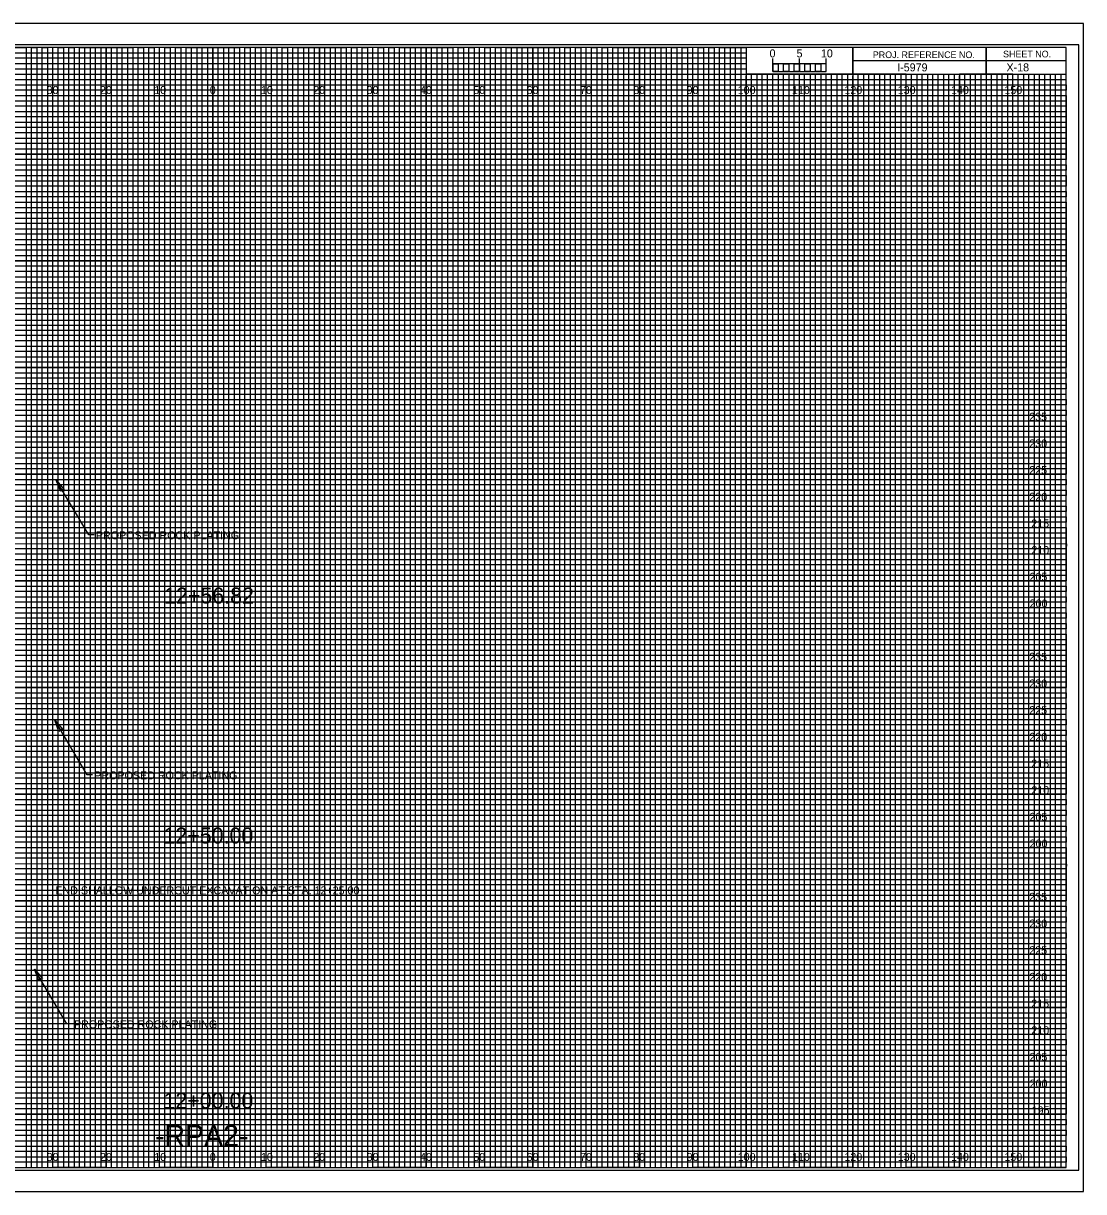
# Model space of a CAD drawing. Extents: x -13 to 323, y -5 to 434.
# Drawn here: x 124.5 to 323.3, y 215.5 to 434.5 of the extents above; entities that cross this region are included whole.
import ezdxf

# ---------------------------------------------------------------- set-up
doc = ezdxf.new("R2010")
doc.units = 0
for name, color, linetype in [('Prop CMT Concrete Structures', 7, 'Continuous'), ('Prop Terminator CELL', 7, 'Continuous'), ('Prop XS Alignment Label', 7, 'Continuous'), ('Prop XS Bar Scale Labels', 7, 'Continuous'), ('Prop XS Elevation Labels', 7, 'Continuous'), ('Prop XS Hydro Elevations', 7, 'Continuous'), ('Prop XS Offset Labels', 7, 'Continuous'), ('Prop XS Project Number', 7, 'Continuous'), ('Prop XS SE Text', 7, 'Continuous'), ('Prop XS Sheet Number', 7, 'Continuous'), ('Prop XS Station Labels', 7, 'Continuous'), ('Sheet Cross Section CELL', 7, 'Continuous'), ('Sheet Cross Section Grid Major CELL', 7, 'Continuous'), ('Sheet Cross Section Grid Middle CELL', 7, 'Continuous'), ('Sheet Cross Section Grid Minor 1 CELL', 7, 'Continuous'), ('Sheet Cross Section Grid Minor 2 CELL', 7, 'Continuous'), ('Sheet Cross Section Scale CELL', 7, 'Continuous'), ('Sheet Cutting Line CELL', 7, 'Continuous'), ('Sheet DOT Grid CELL', 7, 'Continuous'), ('Sheet Plot Border Inside CELL', 7, 'Continuous'), ('Sheet Plot Border Outside CELL', 7, 'Continuous')]:
    doc.layers.add(name, color=color, linetype=linetype)

msp = doc.modelspace()

# ---------------------------------------------------------------- linework, layer by layer
at = {"layer": 'Prop CMT Concrete Structures'}
for points in [[(137.78, 338.61), (136.76, 338.61), (130.68, 348.85)], [(137.47, 293.61), (136.45, 293.61), (130.37, 303.86)], [(133.67, 246.94), (132.65, 246.94), (126.57, 257.18)]]:
    msp.add_lwpolyline(points, dxfattribs=at)
at = {"layer": 'Prop Terminator CELL'}
for points in [[(131.5, 346.72), (130.68, 348.85), (132.18, 347.11), (131.69, 347.15)], [(131.18, 301.73), (130.37, 303.86), (131.87, 302.12), (131.38, 302.16)], [(127.39, 255.05), (126.57, 257.18), (128.07, 255.44), (127.58, 255.49)]]:
    msp.add_lwpolyline(points, close=True, dxfattribs=at)
at = {"layer": 'Sheet Cross Section CELL'}
for p, q in [((305, 430), (305, 425)), ((305, 425), (305, 430)), ((280, 427.5), (280, 425)), ((320, 427.49), (280, 427.49)), ((280, 425), (320, 425))]:
    msp.add_line(p, q, dxfattribs=at)
for points in [[(320, 430), (0, 430), (0, 220), (320, 220)], [(280, 430), (260, 430), (260, 425.03), (280, 425.03)], [(320, 430), (280, 430), (280, 425), (320, 425)]]:
    msp.add_lwpolyline(points, close=True, dxfattribs=at)
at = {"layer": 'Sheet Cross Section Grid Major CELL'}
for p, q in [((130, 430), (120, 430)), ((130, 220), (130, 430)), ((150, 430), (140, 430)), ((140, 430), (140, 220)), ((150, 220), (150, 430)), ((170, 430), (160, 430)), ((160, 430), (160, 220)), ((170, 220), (170, 430)), ((190, 430), (180, 430)), ((180, 430), (180, 220)), ((190, 220), (190, 430)), ((210, 430), (200, 430)), ((200, 430), (200, 220)), ((210, 220), (210, 430)), ((230, 430), (220, 430)), ((220, 430), (220, 220)), ((230, 220), (230, 430)), ((250, 430), (240, 430)), ((240, 430), (240, 220)), ((250, 220), (250, 430)), ((260, 430), (260, 220)), ((270, 220), (270, 425)), ((290, 425), (280, 425)), ((280, 425), (280, 220)), ((290, 220), (290, 425)), ((310, 425), (300, 425)), ((300, 425), (300, 220)), ((310, 220), (310, 425)), ((140, 220), (130, 220)), ((160, 220), (150, 220)), ((180, 220), (170, 220)), ((200, 220), (190, 220)), ((220, 220), (210, 220)), ((240, 220), (230, 220)), ((260, 220), (250, 220)), ((280, 220), (270, 220)), ((300, 220), (290, 220)), ((320, 220), (310, 220)), ((320, 220), (320, 220))]:
    msp.add_line(p, q, dxfattribs=at)
for points in [[(0, 420), (320, 420), (320, 410), (0, 410)], [(0, 400), (320, 400), (320, 390), (0, 390)], [(0, 380), (320, 380), (320, 370), (0, 370)], [(0, 360), (320, 360), (320, 350), (0, 350)], [(0, 340), (320, 340), (320, 330), (0, 330)], [(0, 320), (320, 320), (320, 310), (0, 310)], [(0, 300), (320, 300), (320, 290), (0, 290)], [(0, 280), (320, 280), (320, 270), (0, 270)], [(0, 260), (320, 260), (320, 250), (0, 250)], [(0, 240), (320, 240), (320, 230), (0, 230)]]:
    msp.add_lwpolyline(points, dxfattribs=at)
at = {"layer": 'Sheet Cross Section Grid Middle CELL'}
for points in [[(115, 430), (125, 430), (125, 220), (135, 220), (135, 430), (145, 430), (145, 220), (155, 220), (155, 430), (165, 430), (165, 220), (175, 220), (175, 430), (185, 430), (185, 220), (195, 220), (195, 430), (205, 430), (205, 220), (215, 220), (215, 430), (225, 430), (225, 220), (235, 220), (235, 430), (245, 430), (245, 220), (255, 220), (255, 430), (259.93, 430), (260, 430), (260, 425), (264.99, 425), (264.99, 220), (275, 220), (275, 425), (285, 425), (285, 220), (295, 220), (295, 425), (305, 425), (305, 220), (315, 220), (315, 425)], [(0, 425), (275, 425)], [(0, 405), (320, 405), (320, 415), (0, 415)], [(0, 385), (320, 385), (320, 395), (0, 395)], [(0, 365), (320, 365), (320, 375), (0, 375)], [(0, 345), (320, 345), (320, 355), (0, 355)], [(0, 325), (320, 325), (320, 335), (0, 335)], [(0, 305), (320, 305), (320, 315), (0, 315)], [(0, 285), (320, 285), (320, 295), (0, 295)], [(0, 265), (320, 265), (320, 275), (0, 275)], [(0, 245), (320, 245), (320, 255), (0, 255)], [(0, 225), (320, 225), (320, 235), (0, 235)]]:
    msp.add_lwpolyline(points, dxfattribs=at)
at = {"layer": 'Sheet Cross Section Grid Minor 1 CELL'}
for p, q in [((0, 429), (260, 429)), ((260, 427.98), (0, 427.98)), ((260, 429), (260, 427.98)), ((0, 427), (260, 427)), ((260, 425.89), (0, 425.89)), ((260, 427), (260, 425.89)), ((0, 424), (320, 424))]:
    msp.add_line(p, q, dxfattribs=at)
for points in [[(0, 423), (270, 423), (320, 423), (320, 422), (0, 422)], [(0, 421), (320, 421), (320, 419), (0, 419)], [(0, 418), (320, 418), (320, 417), (0, 416.98)], [(0, 416), (320, 416), (320, 414), (0, 414)], [(0, 413), (320, 413), (320, 412), (0, 412)], [(0, 411), (320, 411), (320, 409), (0, 409)], [(0, 408), (320, 408), (320, 407), (0, 407)], [(0, 406), (320, 406), (320, 404), (0, 404)], [(0, 403), (320, 403), (320, 402), (0, 402)], [(0, 401), (320, 401), (320, 399), (0, 399)], [(0, 398), (320, 398), (320, 397), (0, 397)], [(0, 396), (320, 396), (320, 393.95), (320, 393), (320, 392), (0, 392)], [(0, 394), (320, 394), (320, 393), (0, 393)], [(0, 391), (320, 391), (320, 389), (0, 389.03)], [(0, 389.03), (320, 389), (320, 388), (0, 388)], [(0, 387), (320, 387), (320, 386), (0, 386)], [(0, 384), (320, 384), (320, 383), (0, 383)], [(0, 382), (320, 382), (320, 381), (0, 381)], [(-0.07, 378.89), (320, 378.89), (320, 377.88), (-0.07, 377.88)], [(0, 377), (320, 377), (320, 376), (0, 376)], [(0, 374), (320, 374), (320, 373), (0, 373)], [(0, 372), (320, 372), (320, 371), (0, 371)], [(0, 369), (320, 369), (320, 368), (0, 368)], [(0, 367), (320, 367), (320, 366), (0, 366)], [(0, 364), (320, 364), (320, 363), (0, 363)], [(0, 362), (320, 362), (320, 361), (0, 361)], [(0, 359), (320, 359), (319.99, 357.98), (0, 358)], [(0, 357), (320, 357), (320, 356), (0, 356)], [(0, 354), (320, 354), (320, 353), (0, 353)], [(0, 352), (320, 352), (320, 351), (0, 351)], [(0, 349), (320, 349), (320, 348), (0, 348)], [(0, 347), (320, 347), (320, 346), (0, 346)], [(0, 344), (320, 344), (320, 343), (0, 343)], [(0, 342), (320, 342), (320, 341), (0, 341)], [(0, 339), (320, 339), (320, 338), (0, 338)], [(0, 336.99), (320.07, 336.91), (320, 336), (0, 336)], [(0, 334), (320, 334), (320, 333), (0, 333)], [(0, 332), (320, 332), (320, 331), (0, 331)], [(0, 329), (320, 329), (320, 328), (0, 328)], [(0, 327), (320, 327), (320, 326), (0, 326)], [(0, 324), (320, 324), (320, 323), (0, 323)], [(0, 322), (320, 322), (320, 321), (0, 321)], [(0, 319), (320, 319), (320, 318), (0, 318)], [(0, 317), (320, 317), (320, 316), (0, 316)], [(0, 314), (320, 314), (320, 313), (0, 313)], [(0, 312), (320, 312), (320, 311), (0, 311)], [(0, 309), (320, 309), (320, 308), (0, 308)], [(0, 307), (320, 307), (320, 306), (0, 306)], [(0, 304), (320, 304), (320, 303), (0, 303)], [(0, 302), (320, 302), (320, 301), (0, 301)], [(0, 299), (320, 299), (319.99, 297.98), (0, 298)], [(0, 297), (320, 297), (320, 296), (0, 296)], [(0, 294), (320, 294), (320, 293), (0, 293)], [(0, 292), (320, 292), (320, 291), (0, 291)], [(0, 289), (320, 289), (320, 288), (0, 288)], [(0, 287), (320, 287), (320, 286), (0, 286)], [(0, 284), (320, 284), (320, 283), (0, 283)], [(0, 282), (320, 282), (320, 281), (0, 281)], [(0, 279), (320, 279), (320, 278), (0, 278)], [(0, 276.99), (320.07, 276.91), (320, 276), (0, 276)], [(0, 274), (320, 274), (320, 273), (0, 273)], [(0, 272), (320, 272), (320, 271), (0, 271)], [(0, 269), (320, 269), (320, 268), (0, 268)], [(0, 267), (320, 267), (320, 266), (0, 266)], [(0, 264), (320, 264), (320, 263), (0, 263)], [(0, 262), (320, 262), (320, 261), (0, 261)], [(0, 259), (320, 259), (320, 258), (0, 258)], [(0, 257), (320, 257), (320, 256), (0, 256)], [(0, 254), (320, 254), (320, 253), (0, 253)], [(0, 252), (320, 252), (320, 251), (0, 251)], [(0, 249), (320, 249), (320, 248), (0, 248)], [(0, 247), (320, 247), (320, 246), (0, 246)], [(0, 244), (320, 244), (320, 243), (0, 243)], [(0, 242), (320, 242), (320, 241), (0, 241)], [(0, 239), (320, 239), (320, 238), (0, 238)], [(0, 237), (320, 237), (320, 236), (0, 236)], [(0, 234), (320, 234), (320, 233), (0, 233)], [(0, 232), (320, 232), (320, 231), (0, 231)], [(0, 229), (320, 229), (320, 228), (0, 228)], [(0, 227), (320, 227), (320, 226), (0, 226)], [(0, 224), (320, 224), (320, 223), (0, 223)], [(0, 222), (320, 222), (320, 221), (0, 221)]]:
    msp.add_lwpolyline(points, dxfattribs=at)
at = {"layer": 'Sheet Cross Section Grid Minor 2 CELL'}
for p, q in [((267, 425), (266.01, 425)), ((266.01, 425), (266.01, 220)), ((267, 220), (267, 425)), ((269, 425), (268, 425)), ((268, 425), (268, 220)), ((269, 220), (269, 425)), ((266.01, 220), (265, 220)), ((268, 220), (267, 220))]:
    msp.add_line(p, q, dxfattribs=at)
for points in [[(125, 220), (126, 220), (126, 430), (127, 430), (127, 220)], [(127, 220), (128, 220), (128, 430), (129, 430), (129, 220)], [(130, 220), (131, 220), (131, 430), (132, 430), (132, 220)], [(132, 220), (133, 220), (133, 430), (134, 430), (134, 220)], [(135, 220), (136, 220), (136, 430), (137, 430), (137, 220)], [(137, 220), (138, 220), (138, 430), (139, 430), (139, 220)], [(140, 220), (141, 220), (141, 430), (142, 430), (142, 220)], [(142, 220), (143, 220), (143, 430), (144, 430), (144, 220)], [(145, 220), (146, 220), (146, 430), (147, 430), (147, 220)], [(147, 220), (148, 220), (148, 430), (149, 430), (149, 220)], [(150, 220), (151, 220), (151, 430), (152, 430), (152, 220)], [(152, 220), (153, 220), (153, 430), (154, 430), (154, 220)], [(155, 220), (156, 220), (156, 430), (157, 430), (157, 220)], [(157, 220), (158, 220), (158, 430), (159, 430), (159, 220)], [(160, 220), (161, 220), (161, 430), (162, 430), (162, 220)], [(162, 220), (163, 220), (163, 430), (164, 430), (164, 220)], [(165, 220), (166, 220), (166, 430), (167, 430), (167, 220)], [(167, 220), (168, 220), (168, 430), (169, 430), (169, 220)], [(170, 220), (171, 220), (171, 430), (172, 430), (172, 220)], [(172, 220), (173, 220), (173, 430), (174, 430), (174, 220)], [(175, 220), (176, 220), (176, 430), (177, 430), (177, 220)], [(177, 220), (178, 220), (178, 430), (179, 430), (179, 220)], [(180, 220), (181, 220), (181, 430), (182, 430), (182, 220)], [(182, 220), (183, 220), (183, 430), (184, 430), (184, 220)], [(185, 220), (186, 220), (186, 430), (187, 430), (187, 220)], [(187, 220), (188, 220), (188, 430), (189, 430), (189, 220)], [(190, 220), (191, 220), (191, 430), (192, 430), (192, 220)], [(192, 220), (193, 220), (193, 430), (194, 430), (194, 220)], [(195, 220), (196, 220), (196, 430), (197, 430), (197, 220)], [(197, 220), (198, 220), (198, 430), (199, 430), (199, 220)], [(200, 220), (201, 220), (201, 430), (202, 430), (202, 220)], [(202, 220), (203, 220), (203, 430), (204, 430), (204, 220)], [(205, 220), (206, 220), (206, 430), (207, 430), (207, 220)], [(207, 220), (208, 220), (208, 430), (209, 430), (209, 220)], [(210, 220), (211, 220), (211, 430), (212, 430), (212, 220)], [(212, 220), (213, 220), (213, 430), (214, 430), (214, 220)], [(215, 220), (216, 220), (216, 430), (217, 430), (217, 220)], [(217, 220), (218, 220), (218, 430), (219, 430), (219, 220)], [(220, 220), (221, 220), (221, 430), (222, 430), (222, 220)], [(222, 220), (223, 220), (223, 430), (224, 430), (224, 220)], [(225, 220), (226, 220), (226, 430), (227, 430), (227, 220)], [(227, 220), (228, 220), (228, 430), (229, 430), (229, 220)], [(230, 220), (231, 220), (231, 430), (232, 430), (232, 220)], [(232, 220), (233, 220), (233, 430), (234, 430), (234, 220)], [(235, 220), (236, 220), (236, 430), (237, 430), (237, 220)], [(237, 220), (238, 220), (238, 430), (239, 430), (239, 220)], [(240, 220), (241, 220), (241, 430), (242, 430), (242, 220)], [(242, 220), (243, 220), (243, 430), (244, 430), (244, 220)], [(245, 220), (246, 220), (246, 430), (247, 430), (247, 220)], [(247, 220), (248, 220), (248, 430), (249, 430), (249, 220)], [(250, 220), (251, 220), (251, 430), (252, 430), (252, 220)], [(252, 220), (253, 220), (253, 430), (254, 430), (254, 220)], [(255, 220), (256, 220), (256, 430), (257, 430), (257, 220)], [(257, 220), (258, 220), (258, 430), (259, 430), (259, 220)], [(260, 220), (261, 220), (261, 425), (262.02, 425), (262.02, 220)], [(262, 220), (263, 220), (263, 425), (263.99, 425), (263.99, 220)], [(270, 220), (270.98, 220), (270.98, 425), (272, 425), (272, 220)], [(272, 220), (273, 220), (273, 425), (274.05, 425), (274.05, 220)], [(275, 220), (276, 220), (276, 425), (277, 425), (277, 220)], [(277, 220), (278, 220), (278, 425), (279, 425), (279, 220)], [(280, 220), (281, 220), (281, 425), (282, 425), (282, 220)], [(282, 220), (283, 220), (283, 425), (284, 425), (284, 220)], [(285, 220), (286, 220), (286, 425), (287, 425), (287, 220)], [(287, 220), (288, 220), (288, 425), (289, 425), (289, 220)], [(290, 220), (291, 220), (291, 425), (292, 425), (292, 220)], [(292, 220), (293, 220), (293, 425), (294, 425), (294, 220)], [(295, 220), (296, 220), (296, 425), (297, 425), (297, 220)], [(297, 220), (298, 220), (298, 425), (299, 425), (299, 220)], [(300, 220), (301, 220), (301, 425), (302, 425), (302, 220)], [(302, 220), (303, 220), (303, 425), (304, 425), (304, 220)], [(305, 220), (306, 220), (306, 425), (307, 425), (307, 220)], [(307, 220), (308, 220), (308, 425), (309, 425), (309, 220)], [(310, 220), (311, 220), (311, 425), (312, 425), (312, 220)], [(312, 220), (313, 220), (313, 425), (314, 425), (314, 220)], [(315, 220), (316, 220), (316, 425), (317, 425), (317, 220)], [(317, 220), (318, 220), (318, 425), (319, 425), (319, 220)]]:
    msp.add_lwpolyline(points, dxfattribs=at)
at = {"layer": 'Sheet Cross Section Scale CELL'}
for p, q in [((265, 425.49), (265, 427.9)), ((265, 426.9), (265, 427.9)), ((270, 425.49), (270, 427.9)), ((275, 425.49), (275, 427.9)), ((275, 426.9), (275, 427.9))]:
    msp.add_line(p, q, dxfattribs=at)
for points in [[(275, 426.9), (265, 426.9), (265, 425.49), (275, 425.49)], [(265, 426.9), (266, 426.9), (266, 425.49), (265, 425.49)], [(267, 426.9), (268, 426.9), (268, 425.49), (267, 425.49)], [(269, 426.9), (270, 426.9), (270, 425.49), (269, 425.49)], [(271, 426.9), (272, 426.9), (272, 425.49), (271, 425.49)], [(273, 426.9), (274, 426.9), (274, 425.49), (273, 425.49)]]:
    msp.add_lwpolyline(points, close=True, dxfattribs=at)
at = {"layer": 'Sheet Cutting Line CELL'}
for p, q in [((323.3, 434.5), (-13.4, 434.5)), ((-13.4, 215.5), (323.3, 215.5))]:
    msp.add_line(p, q, dxfattribs=at)
at = {"layer": 'Sheet DOT Grid CELL'}
for p, q in [((130, 220), (130, 430)), ((140, 220), (140, 430)), ((150, 220), (150, 430)), ((160, 220), (160, 430)), ((170, 220), (170, 430)), ((180, 220), (180, 430)), ((190, 220), (190, 430)), ((200, 220), (200, 430)), ((210, 220), (210, 430)), ((220, 220), (220, 430)), ((230, 220), (230, 430)), ((240, 220), (240, 430)), ((250, 220), (250, 430)), ((260, 220), (260, 424.69)), ((270, 220), (270, 424.69)), ((280, 220), (280, 424.69)), ((290, 220), (290, 424.69)), ((300, 220), (300, 424.69)), ((310, 220), (310, 424.69)), ((0, 420), (320, 420)), ((0, 410), (320, 410)), ((0, 400), (320, 400)), ((0, 390), (320, 390)), ((0, 380), (320, 380)), ((0, 370), (320, 370)), ((0, 360), (320, 360)), ((0, 350), (320, 350)), ((0, 340), (320, 340)), ((0, 330), (320, 330)), ((0, 320), (320, 320)), ((0, 310), (320, 310)), ((0, 300), (320, 300)), ((0, 290), (320, 290)), ((0, 280), (320, 280)), ((0, 270), (320, 270)), ((0, 260), (320, 260)), ((0, 250), (320, 250)), ((0, 240), (320, 240)), ((0, 230), (320, 230))]:
    msp.add_line(p, q, dxfattribs=at)
at = {"layer": 'Sheet Plot Border Inside CELL'}
msp.add_lwpolyline([(-10.8, 219.5), (322.4, 219.5), (322.4, 430.5), (-10.8, 430.5)], close=True, dxfattribs=at)
at = {"layer": 'Sheet Plot Border Outside CELL'}
msp.add_lwpolyline([(-13.4, 215.5), (323.3, 215.5), (323.3, 434.5), (-13.4, 434.5)], close=True, dxfattribs=at)

# ---------------------------------------------------------------- texts
at = {"layer": 'Prop XS Alignment Label'}
msp.add_text('-RPA2-', height=4, dxfattribs=at).set_placement((149.17, 224))
at = {"layer": 'Prop XS Bar Scale Labels'}
for s, p in [('5', (269.47, 428.12)), ('10', (274.04, 428.12))]:
    msp.add_text(s, height=1.5, dxfattribs=at).set_placement(p)
at = {"layer": 'Prop XS Elevation Labels'}
for s, p in [('235', (313.09, 360)), ('230', (313.11, 355)), ('225', (313.1, 350)), ('220', (313.12, 345)), ('215', (313.48, 340)), ('210', (313.5, 335)), ('205', (313.15, 330)), ('200', (313.17, 325)), ('235', (313.09, 315)), ('230', (313.11, 310)), ('225', (313.1, 305)), ('220', (313.12, 300)), ('215', (313.48, 295)), ('210', (313.5, 290)), ('205', (313.15, 285)), ('200', (313.17, 280)), ('235', (313.09, 270)), ('230', (313.11, 265)), ('225', (313.1, 260)), ('220', (313.12, 255)), ('215', (313.48, 250)), ('210', (313.5, 245)), ('205', (313.15, 240)), ('200', (313.17, 235)), ('195', (313.55, 230))]:
    msp.add_text(s, height=1.5, dxfattribs=at).set_placement(p)
at = {"layer": 'Prop XS Hydro Elevations'}
msp.add_text('END SHALLOW UNDERCUT EXCAVATION AT STA. 12+25.00', height=1.5, dxfattribs=at).set_placement((130.5, 271.22))
at = {"layer": 'Prop XS Offset Labels'}
for s, p in [('30', (128.86, 421.25)), ('20', (138.86, 421.25)), ('10', (149.04, 421.25)), ('0', (159.45, 421.25)), ('0', (159.45, 421.25)), ('10', (169.04, 421.25)), ('20', (178.86, 421.25)), ('30', (188.86, 421.25)), ('40', (198.86, 421.25)), ('50', (208.86, 421.25)), ('60', (218.86, 421.25)), ('70', (228.86, 421.25)), ('80', (238.86, 421.25)), ('90', (248.86, 421.25)), ('100', (258.44, 421.25)), ('110', (268.62, 421.25)), ('120', (278.44, 421.25)), ('130', (288.44, 421.25)), ('140', (298.44, 421.25)), ('150', (308.44, 421.25)), ('30', (128.86, 221.25)), ('20', (138.86, 221.25)), ('10', (149.04, 221.25)), ('0', (159.45, 221.25)), ('0', (159.45, 221.25)), ('10', (169.04, 221.25)), ('20', (178.86, 221.25)), ('30', (188.86, 221.25)), ('40', (198.86, 221.25)), ('50', (208.86, 221.25)), ('60', (218.86, 221.25)), ('70', (228.86, 221.25)), ('80', (238.86, 221.25)), ('90', (248.86, 221.25)), ('100', (258.44, 221.25)), ('110', (268.62, 221.25)), ('120', (278.44, 221.25)), ('130', (288.44, 221.25)), ('140', (298.44, 221.25)), ('150', (308.44, 221.25))]:
    msp.add_text(s, height=1.5, dxfattribs=at).set_placement(p)
at = {"layer": 'Prop XS Project Number'}
msp.add_text('I-5979', height=1.5, dxfattribs=at).set_placement((288.34, 425.5))
at = {"layer": 'Prop XS SE Text'}
for p in [(138.1, 337.78), (137.79, 292.78), (133.99, 246.11)]:
    msp.add_text('PROPOSED ROCK PLATING', height=1.5, rotation=360, dxfattribs=at).set_placement(p)
at = {"layer": 'Prop XS Sheet Number'}
msp.add_text('X-18', height=1.5, dxfattribs=at).set_placement((308.83, 425.5))
at = {"layer": 'Prop XS Station Labels'}
for s, p in [('12+56.82', (150.89, 325.74)), ('12+50.00', (150.77, 280.76)), ('12+00.00', (150.77, 231.06))]:
    msp.add_text(s, height=3, dxfattribs=at).set_placement(p)
at = {"layer": 'Sheet Cross Section CELL'}
for s, p in [('PROJ. REFERENCE NO.', (283.77, 427.99)), ('SHEET NO.', (308.19, 428.12))]:
    msp.add_text(s, height=1.25, dxfattribs=at).set_placement(p)
at = {"layer": 'Sheet Cross Section Scale CELL'}
msp.add_text('0', height=1.5, dxfattribs=at).set_placement((264.41, 428.12))

doc.saveas('drawing.dxf')
